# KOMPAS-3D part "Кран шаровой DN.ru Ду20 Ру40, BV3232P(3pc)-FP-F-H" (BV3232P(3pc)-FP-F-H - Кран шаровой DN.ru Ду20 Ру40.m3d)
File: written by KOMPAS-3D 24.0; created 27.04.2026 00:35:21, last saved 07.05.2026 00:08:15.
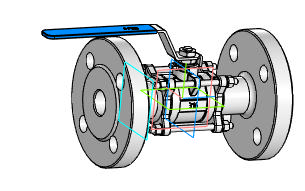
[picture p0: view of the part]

Document properties: Автор: Максим; Полное имя файла: BVxxP(3pc)-FP-F-H - Кран шаровой DN.ru Ду20 Ру40.cdw

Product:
- Body: Тело 1  | qty 1
    Масса: 2.799739
- Part/product: Кран шаровой DN.ru Ду20 Ру40  | designation BV3232P(3pc)-FP-F-H
    Масса: 2.71
    Раздел спецификации: Прочие изделия
    Форматы листов документа: A3
    Примечание: D160-22802

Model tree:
1. Операция без истории:1
2. Эскиз:1  (with: Ребро.Операция без истории:1)
3. Эскиз:5  (with: Грань.Операция без истории:1)
4. Элемент выдавливания:4
     Расстояние 2 = 15
5. Элемент выдавливания:5  (with: Грань.Элемент выдавливания:4, Грань.Операция без истории:1)
     Расстояние 1 = 12.75
6. Эскиз:6  (with: Грань.Операция без истории:1)
7. Элемент выдавливания:6
     Расстояние 1 = 2
8. Элемент выдавливания:7
     Расстояние 1 = 5
9. Эскиз:8  (with: Ребро.Элемент выдавливания:7)
10. Элемент выдавливания:8
     Расстояние 1 = 15
11. Фаска:1  (with: Ребро.Элемент выдавливания:8)
     Угол = 45; Длина 1 = 4; Длина 2 = 4
12. Эскиз:9  (with: Ребро.Элемент выдавливания:8)
13. Элемент выдавливания:9
     Расстояние 1 = 16
14. Скругление:1  (with: Ребро.Элемент выдавливания:9)
     Радиус = 5
15. Скругление:2  (with: Ребро.Элемент выдавливания:9)
     Радиус = 0.5
16. Скругление:3  (with: Ребро.Элемент выдавливания:7)
     Радиус = 1
17. Скругление:4  (with: Ребро.Элемент выдавливания:7)
     Радиус = 3
18. Эскиз:10  (with: Грань.Операция без истории:1, Ребро.Операция без истории:1)
19. Элемент выдавливания:10  (with: Грань.Операция без истории:1)
     Расстояние 2 = 150
20. Смещенная плоскость:1
     Расстояние = -42
21. Эскиз:11  (with: Ребро.Операция без истории:1)
22. Элемент выдавливания:11
     Расстояние 1 = 10; Расстояние 2 = 10
23. Зеркальный массив:1
24. Экземпляр ( 1 )
25. Экземпляр ( 2 )  (with: Элемент выдавливания:11)
26. Эскиз:12  (with: Грань.Операция без истории:1)
27. Элемент выдавливания:12
     Расстояние 1 = 10
28. Эскиз:13  (with: Грань.Операция без истории:1)
29. Элемент выдавливания:13
     Расстояние 1 = 0.2
30. Фаска:2  (with: Ребро.Элемент выдавливания:6)
     Угол = 45; Длина 1 = 1; Длина 2 = 1
31. Эскиз:14  (with: Грань.Элемент выдавливания:9, Ребро.Элемент выдавливания:9, Ребро.Скругление:2)
32. Элемент выдавливания:14
     Расстояние 2 = 0.2
33. Эскиз:15  (with: Грань.Операция без истории:1)
34. Элемент выдавливания:15
     Расстояние 1 = 0.2

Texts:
  Точка начала. Х
  Точка начала. Y
  Точка начала. Z
  BV3232P(3pc)-FP-F-H
  DN20 PN40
